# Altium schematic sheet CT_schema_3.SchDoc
size 461 x 227 mm
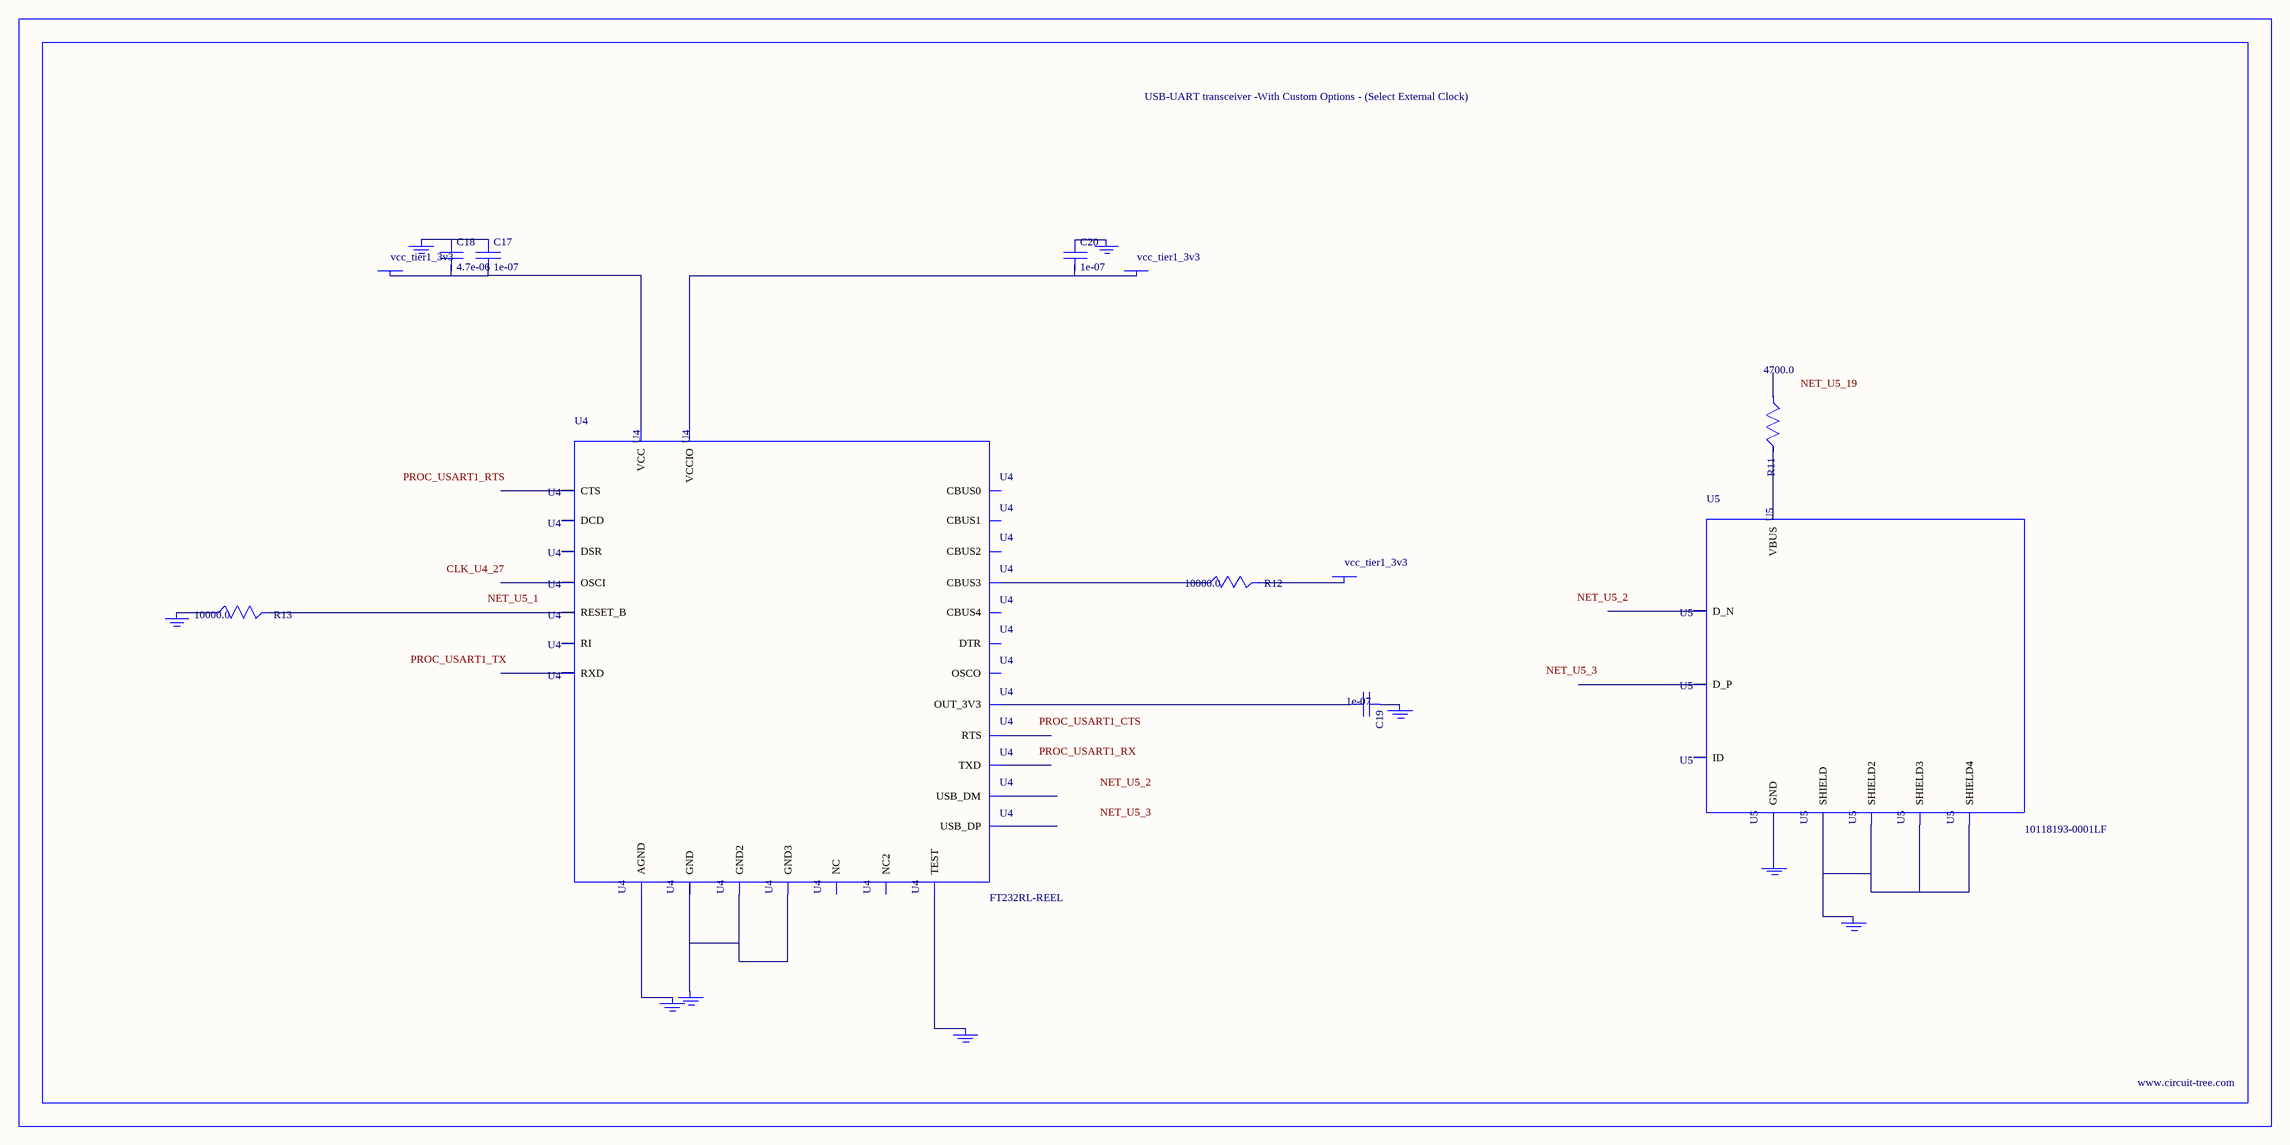
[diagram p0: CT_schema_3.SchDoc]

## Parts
BORDER2  (no value)
C17  1e-07  [C0402]
C18  4.7e-06  [C0805]
C19  1e-07  [C0402]
C20  1e-07  [C0402]
GND_INSTANCE_2_0  (no value)
GND_INSTANCE_2_1  (no value)
GND_INSTANCE_2_2  (no value)
GND_INSTANCE_2_3  (no value)
GND_INSTANCE_2_4  (no value)
GND_INSTANCE_2_5  (no value)
GND_INSTANCE_2_6  (no value)
GND_INSTANCE_2_7  (no value)
GND_INSTANCE_2_8  (no value)
POWER_INSTANCE_2_0  vcc_tier1_3v3
POWER_INSTANCE_2_1  vcc_tier1_3v3
POWER_INSTANCE_2_2  vcc_tier1_3v3
R11  4700.0  [R0603]
R12  10000.0  [R0603]
R13  10000.0  [R0603]
U4  FT232RL-REEL  [SSOP-28]
U5  10118193-0001LF  [FCI_10118193-0001LF]

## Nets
NetC17_1: C17.1 C18.1 GND_INSTANCE_2_3.0(GND)
NetC17_2: C17.2 C18.2 POWER_INSTANCE_2_2.0(PWR) U4.20(VCC)
NetC19_1: C19.1 GND_INSTANCE_2_1.0(GND)
NetC19_2: C19.2 U4.17(OUT_3V3)
NetC20_1: C20.1 GND_INSTANCE_2_0.0(GND)
NetC20_2: C20.2 POWER_INSTANCE_2_0.0(PWR) U4.4(VCCIO)
NetGND_INSTANCE_2_2_0: GND_INSTANCE_2_2.0(GND) R13.1
NetGND_INSTANCE_2_4_0: GND_INSTANCE_2_4.0(GND) U4.25(AGND)
NetGND_INSTANCE_2_5_0: GND_INSTANCE_2_5.0(GND) U4.26(TEST)
NetGND_INSTANCE_2_6_0: GND_INSTANCE_2_6.0(GND) U4.7(GND) U4.18(GND2) U4.21(GND3)
NetGND_INSTANCE_2_7_0: GND_INSTANCE_2_7.0(GND) U5.6(SHIELD) U5.7(SHIELD2) U5.8(SHIELD3) U5.9(SHIELD4)
NetGND_INSTANCE_2_8_0: GND_INSTANCE_2_8.0(GND) U5.5(GND)
NetPOWER_INSTANCE_2_1_0: POWER_INSTANCE_2_1.0(PWR) R12.2
NetR11_2: R11.2 U5.1(VBUS)
NetR12_1: R12.1 U4.14(CBUS3)
NetR13_2: R13.2 U4.19(RESET_B)

Not connected (* = marked no-connect by the designer): R11 1; U4 1(TXD) 2(DTR) 3(RTS) 5(RXD) 6(RI) 8(NC) 9(DSR) 10(DCD) 11(CTS) 12(CBUS4) 13(CBUS2) 15(USB_DP) 16(USB_DM) 22(CBUS1) 23(CBUS0) 24(NC2) 27(OSCI) 28(OSCO); U5 2(D_N) 3(D_P) 4(ID)

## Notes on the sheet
- Labels drawn without touching a wire or pin: CLK_U4_27, NET_U5_1, NET_U5_2, NET_U5_3, NET_U5_19, PROC_USART1_CTS, PROC_USART1_RTS, PROC_USART1_RX, PROC_USART1_TX

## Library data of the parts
BORDER2 = BORDER_PAGE2
C17 C19 C20 = C0402C104K3RACTU
C18 = C0805C475K4RACTU
GND_INSTANCE_2_0-GND_INSTANCE_2_8 = GND
POWER_INSTANCE_2_0-POWER_INSTANCE_2_2 = PWR
R11 = RC0603JR-074K7L
R12 R13 = RC0603JR-0710KL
